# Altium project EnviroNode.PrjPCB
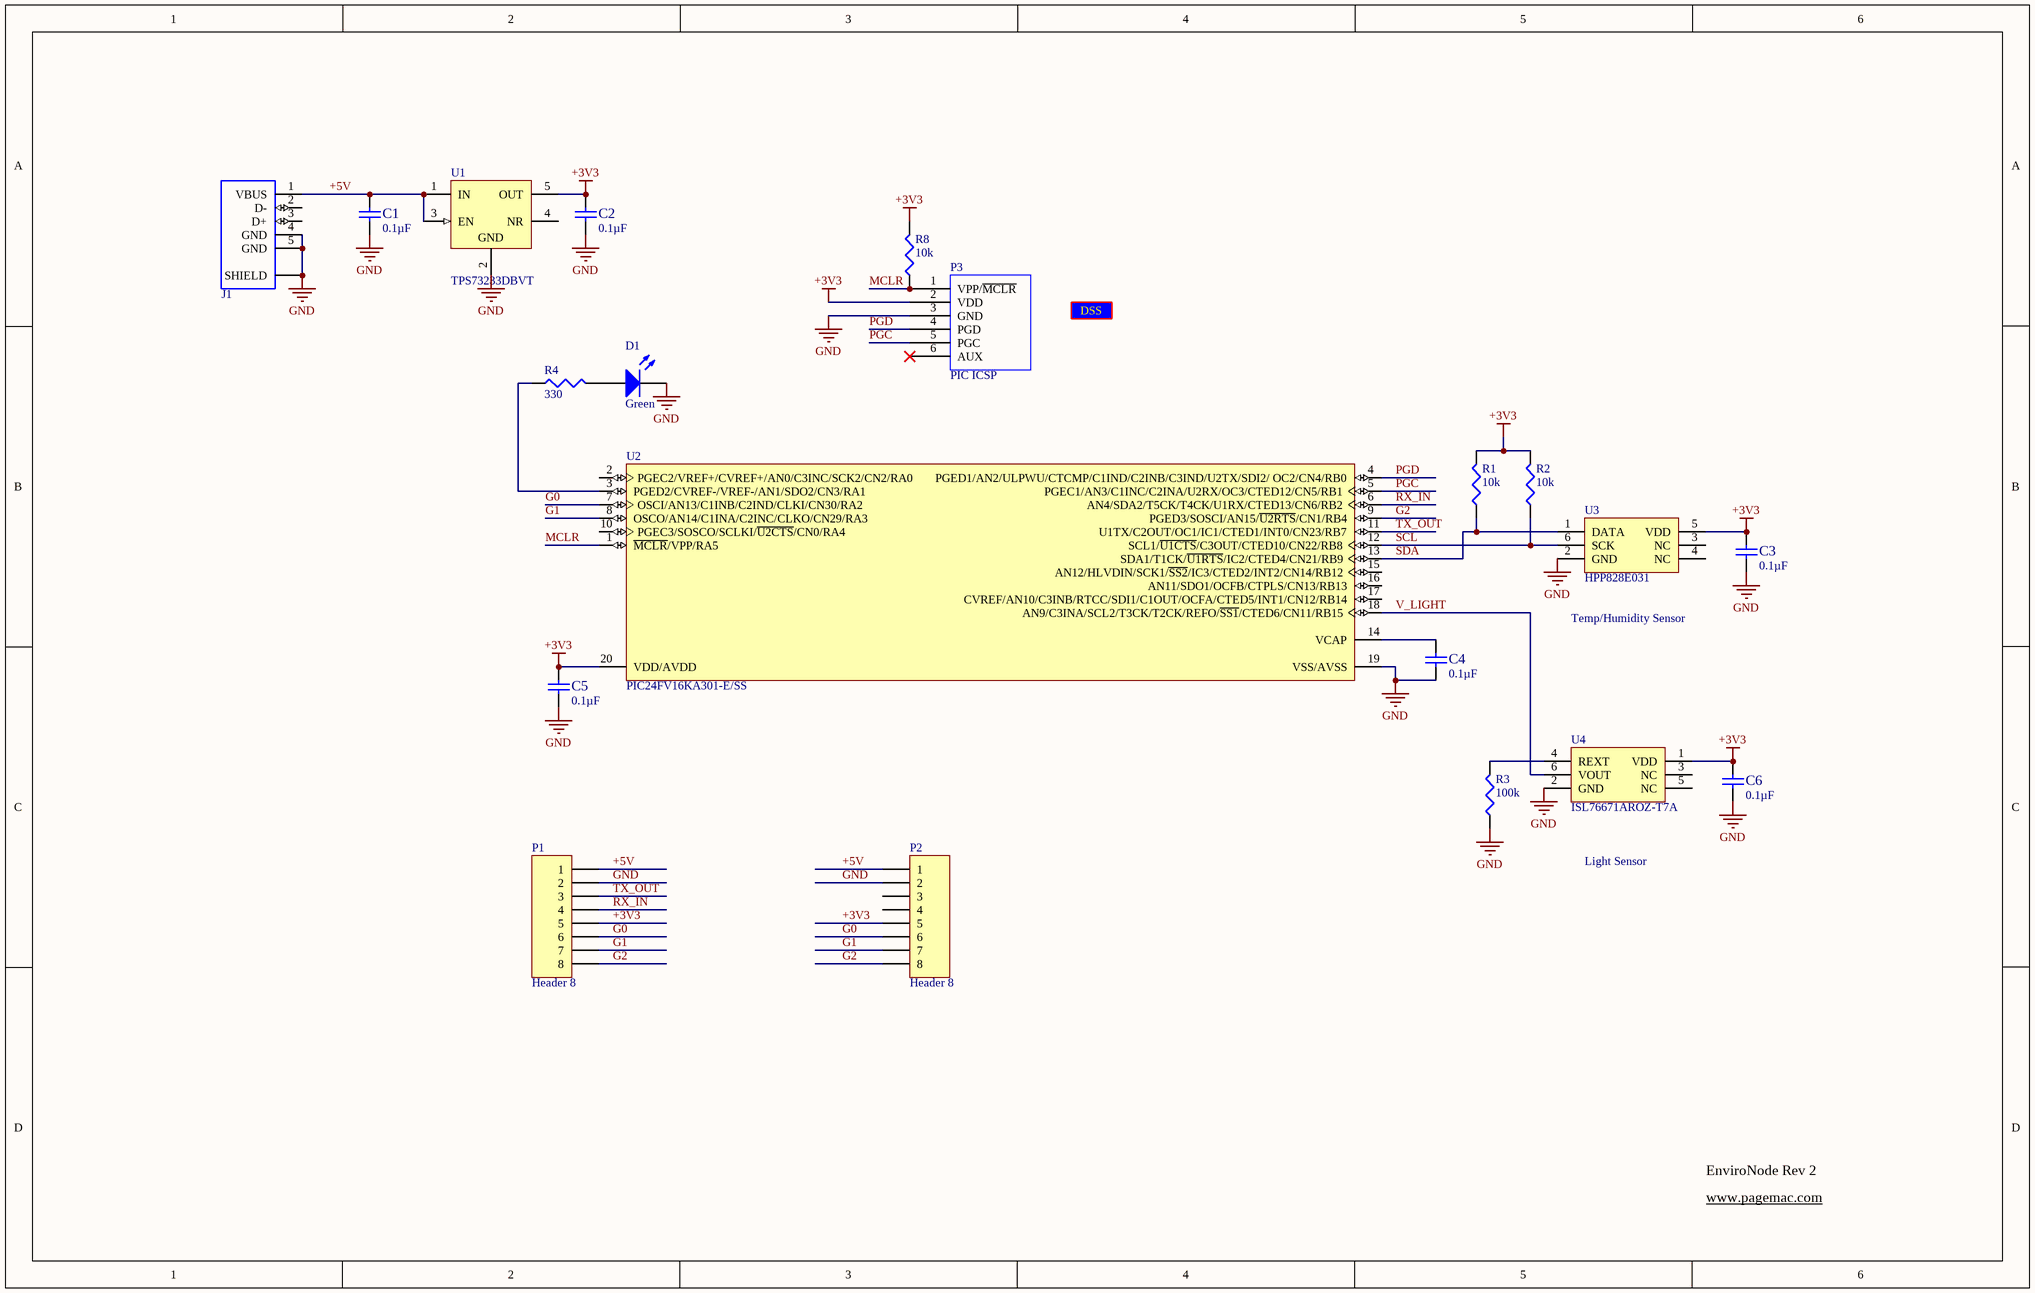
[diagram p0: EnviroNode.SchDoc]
1 sheet, 21 parts. Net scope: global (net labels, ports and power ports of the same name join across sheets).
Board file: EnviroNode.PcbDoc

## Sheet EnviroNode.SchDoc
size B; Scale: NONE; CageCode: 1FEZ4; Contract_No: DAAH01-XX-X-XXXX; Next_Assy: XXYYY-ZZZZZ; Used_On: USED ON; DrawnDate: YYYY/MM/DD; CheckDate: YYYY/MM/DD; EngineerDate: YYYY/MM/DD

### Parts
C1  Capacitance: 0.1µF  [C0603]  (hidden comment: CC0603KRX7R9BB104)
C2  Capacitance: 0.1µF  [C0603]  (hidden comment: CC0603KRX7R9BB104)
C3  Capacitance: 0.1µF  [C0603]  (hidden comment: CC0603KRX7R9BB104)
C4  Capacitance: 0.1µF  [C0603]  (hidden comment: CC0603KRX7R9BB104)
C5  Capacitance: 0.1µF  [C0603]  (hidden comment: CC0603KRX7R9BB104)
C6  Capacitance: 0.1µF  [C0603]  (hidden comment: CC0603KRX7R9BB104)
D1  Color: Green  [LED_0603]  (hidden comment: LTST-C190KGKT)
J1  10118192-0001LF  [FCI/10118192-0001LF]  (value not drawn)
P1  Header 8  [HDR1X8]
P2  Header 8  [HDR1X8]
P3  PIC ICSP  [HDR1X6]  (no BOM)
R1  Resistance (Ohms): 10k  [R0603]  (hidden comment: ERJ-3EKF1002V)
R2  Resistance (Ohms): 10k  [R0603]  (hidden comment: ERJ-3EKF1002V)
R3  Resistance (Ohms): 100k  [R0603]  (hidden comment: ERJ-3EKF1003V)
R4  Resistance (Ohms): 330  [R0603]  (hidden comment: ERJ-3GEYJ331V)
R8  Resistance (Ohms): 10k  [R0603]  (hidden comment: ERJ-3EKF1002V)
SS1  DSS  [DSS_LOGO]  (value not drawn)
U1  TPS73233DBVT  [TI-DBV5_N]
U2  PIC24FV16KA301-E/SS  [MCHP-SSOP-SS20_N]
U3  HPP828E031  [DFN-6]
U4  ISL76671AROZ-T7A  [ODFN-6]

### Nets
+3V3: C2.1 C3.1 C5.1 C6.1 P1.5 P2.5 P3.2(VDD) R1.2 R2.2 R8.2 U1.5(OUT) U2.20(VDD/AVDD) U3.5(VDD) U4.1(VDD)
GND: C1.2 C2.2 C3.2 C4.2 C5.2 C6.2 D1.2 J1.4(GND) J1.5(GND) J1.6(SHIELD) P1.2 P2.2 P3.3(GND) R3.1 U1.2(GND) U2.19(VSS/AVSS) U3.2(GND) U4.2(GND)
+5V: C1.1 J1.1(VBUS) P1.1 P2.1 U1.1(IN) U1.3(EN)
G0: P1.6 P2.6 U2.7(OSCI/AN13/C1INB/C2IND/CLKI/CN30/RA2)
G1: P1.7 P2.7 U2.8(OSCO/AN14/C1INA/C2INC/CLKO/CN29/RA3)
G2: P1.8 P2.8 U2.9(PGED3/SOSCI/AN15/~{U2RTS}/CN1/RB4)
MCLR: P3.1(VPP/~{MCLR}) R8.1 U2.1(~{MCLR}/VPP/RA5)
PGC: P3.5(PGC) U2.5(PGEC1/AN3/C1INC/C2INA/U2RX/OC3/CTED12/CN5/RB1)
PGD: P3.4(PGD) U2.4(PGED1/AN2/ULPWU/CTCMP/C1IND/C2INB/C3IND/U2TX/SDI2/_OC2/CN4/RB0)
RX_IN: P1.4 U2.6(AN4/SDA2/T5CK/T4CK/U1RX/CTED13/CN6/RB2)
SCL: R2.1 U2.12(SCL1/~{U1CTS}/C3OUT/CTED10/CN22/RB8) U3.6(SCK)
SDA: R1.1 U2.13(SDA1/T1CK/~{U1RTS}/IC2/CTED4/CN21/RB9) U3.1(DATA)
TX_OUT: P1.3 U2.11(U1TX/C2OUT/OC1/IC1/CTED1/INT0/CN23/RB7)
V_LIGHT: U2.18(AN9/C3INA/SCL2/T3CK/T2CK/REFO/~{SS1}/CTED6/CN11/RB15) U4.6(VOUT)
NetC4_1: C4.1 U2.14(VCAP)
NetD1_1: D1.1 R4.2
NetR3_2: R3.2 U4.4(REXT)
NetR4_1: R4.1 U2.3(PGED2/CVREF-/VREF-/AN1/SDO2/CN3/RA1)

Not connected (* = marked no-connect by the designer): J1 2(D-) 3(D+); P2 3 4; P3 6(AUX)*; U1 4(NR); U2 2(PGEC2/VREF+/CVREF+/AN0/C3INC/SCK2/CN2/RA0) 10(PGEC3/SOSCO/SCLKI/~{U2CTS}/CN0/RA4) 15(AN12/HLVDIN/SCK1/~{SS2}/IC3/CTED2/INT2/CN14/RB12) 16(AN11/SDO1/OCFB/CTPLS/CN13/RB13) 17(CVREF/AN10/C3INB/RTCC/SDI1/C1OUT/OCFA/CTED5/INT1/CN12/RB14); U3 3(NC) 4(NC); U4 3(NC) 5(NC)

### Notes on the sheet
- Temp/Humidity Sensor
- Light Sensor
- EnviroNode Rev 2
- www.pagemac.com

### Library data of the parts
C1-C6 = CC0603KRX7R9BB104: CAP CER 0.1UF 50V 10% X7R 0603; Manufacturer: Yageo
D1 = LTST-C190KGKT: LED GREEN CLEAR 0603 SMD; Manufacturer: Lite-On Inc; Wavelength - Dominant: 571nm; Wavelength - Peak: 574nm; Millicandela Rating: 35mcd; Voltage - Forward (Vf) Typ: 2V; Current - Test: 20mA; Viewing Angle: 130°; Lens Style/Size: Rectangle with Flat Top, 1.06mm x 0.8mm
J1 = 10118192-0001LF: CONN USB MICRO B RECPT SMT R/A; Manufacturer: FCI; Connector Type: USB - micro B; Number of Contacts: 5; Gender: Receptacle; Specifications: USB 2.0
P1 P2 = Header 8: Header, 8-Pin
P3 = PIC_ICSP: Microchip PIC In-Circuit Serial Programmer Connector
R1 R2 R8 = ERJ-3EKF1002V: RES 10.0K OHM 1/10W 1% 0603 SMD; Manufacturer: Panasonic Electronic Components; Power (Watts): 0.1W, 1/10W; Temperature Coefficient: ±100ppm/°C
R3 = ERJ-3EKF1003V: RES 100K OHM 1/10W 1% 0603 SMD; Manufacturer: Panasonic Electronic Components; Power (Watts): 0.1W, 1/10W; Temperature Coefficient: ±100ppm/°C
R4 = ERJ-3GEYJ331V: RES 330 OHM 1/10W 5% 0603 SMD; Manufacturer: Panasonic Electronic Components; Power (Watts): 0.1W, 1/10W; Temperature Coefficient: ±200ppm/°C
U1 = TPS73233DBVT: Single Output Fast Transient Response LDO, 200 mA, Fixed 3.3 V Output, 1.7 to 5.5 V Input, with Reverse Current Protection, 5-pin SOT-23 (DBV), -40 to 85 degC, Green (RoHS & no Sb/Br); Manufacturer: Texas Instruments; Accuracy(%): 1; Fixed Output Options(V): 3.3; Iout(Max)(A): 0.25; Iq(Typ)(mA): 0.4; SubFamily: Single Channel LDO; Vdo(Typ)(mV): 40; Vin(Max)(V): 5.5; Vin(Min)(V): 1.7
U2 = PIC24FV16KA301-E/SS: General Purpose, 16-Bit Flash Microcontroller with XLP Technology, 16 MIPS, 18 I/O, -40 to 125 degC, 20-pin SSOP (SS20), Tube; Manufacturer: Microchip
U3 = HPP828E031: IC SENSOR TEMP/HUM DGTL; Manufacturer: Measurement Specialties Inc.; Sensor Type: Humidity and Temperature; Humidity Range: 0 ~ 100% RH; Accuracy: ±2% RH; Response Time: 5s; Output: Digital, I²C; Voltage - Supply: 1.5 V ~ 3.6 V
U4 = ISL76671AROZ-T7A: IC AMBIENT LIGHT SENSOR; Manufacturer: Intersil; With Proximity Sensor: No; Wavelength: 550nm; Voltage - Supply: 1.8 V ~ 3 V; Output Type: Current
